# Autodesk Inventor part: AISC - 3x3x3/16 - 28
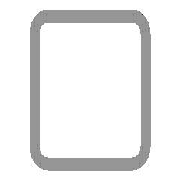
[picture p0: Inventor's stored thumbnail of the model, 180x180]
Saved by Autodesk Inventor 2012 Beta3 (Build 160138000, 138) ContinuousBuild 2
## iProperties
_CCFamilyMember: 9
_CCFamilyDisplayName: ANSI AISC (Square) - Tube
_FrameMemberDoc: Frame Member File
_Version: 15.0.0
_GetPNFromCC: 1
Created: 2010-11
Part Number: AISC - 3x3x3/16 - 28
Material: Steel, Mild
Description: Tube
Document SubType Name: Modeling
Standard: ANSI
Designer: Beta-8540w
Standards Organization: ANSI
Language: en-US
Size Designation: 3x3x3/16
Categories: <MemberInstance><Categories><Category DisplayName="Structural Shapes" InternalName="089c4875-fa83-4c05-b084-43b9cc11f5ed" Mnemonic="GRDR"><CategoryParameter Dis
Stock Number: 3x3x3/16
Density: 7.86 g/cm^3
IsCustomPart: 1
G_L: 28.000 in
G_W: 3.000 in
G_H: 3.000 in
Author: Beta-8540w
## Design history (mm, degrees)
node "Start plane"
node "End plane"
sketch "Sketch"
  geometry: L1 (-38.1, -28.575)-(-38.1, 28.575); L2 (-28.575, 38.1)-(28.575, 38.1); L3 (38.1, 28.575)-(38.1, -28.575); L4 (28.575, -38.1)-(-28.575, -38.1); L5 (-28.575, 33.337)-(28.575, 33.338); L6 (33.338, 28.575)-(33.338, -28.575); L7 (28.575, -33.337)-(-28.575, -33.338); L8 (-33.338, -28.575)-(-33.338, 28.575); L9 (0, 56.102)-(0, -56.102) reference; L10 (-56.102, 0)-(56.102, 0) reference; A1 r 9.525 centre (-28.575, -28.575) between (-38.1, -28.575) and (-28.575, -38.1); A2 r 9.525 centre (-28.575, 28.575) between (-28.575, 38.1) and (-38.1, 28.575); A3 r 9.525 centre (28.575, 28.575) between (38.1, 28.575) and (28.575, 38.1); A4 r 9.525 centre (28.575, -28.575) between (28.575, -38.1) and (38.1, -28.575); A5 r 4.763 centre (-28.575, 28.575) between (-28.575, 33.337) and (-33.338, 28.575); A6 r 4.763 centre (28.575, 28.575) between (33.338, 28.575) and (28.575, 33.338); A7 r 4.763 centre (28.575, -28.575) between (28.575, -33.337) and (33.338, -28.575); A8 r 4.763 centre (-28.575, -28.575) between (-33.338, -28.575) and (-28.575, -33.338)
  constraints: 16 end point, 16 point on circle, 8 centre point, 8 tangent, 4 parallel, 3 equal radius, 2 perpendicular, 7 other
  dimensions: "d10" = 76.2 distance between parallel lines of L2 L4 (= G_H); "d11" = 76.2 distance between parallel lines of L1 L3 (= G_W); "d12" = 4.7625 distance between parallel lines of L3 L6 (= G_T); "d15" = 38.1 distance between parallel lines of L2 L10 (= 0.5 x d10); "d16" = 38.1 distance between parallel lines of L9 L3 (= 0.5 x d11); "d17" = 9.525 radius of A1 (= G_IR)
extrude "Body" new body sketch "Sketch" stored distance "d3" = 711.2 (= G_L); taper "d4" = 0 deg
node "Driven Length"
  sketch "Sketch3"
    geometry: L1 (0, 0)-(10, 0) reference
    constraints: 2 end point, 1 horizontal
  workplane "Work Plane3"
  sketch "Sketch4"
    geometry: L1 (-2, 0)-(12, 0) reference; L2 (-2, 711.2)-(12, 711.2) reference
    dimensions: "d19" = 711.2 distance between parallel lines of L1 L2 (derived)
body "Solid1"
other parameters: "G_W" = 76.2 [user parameter; used in 1 equation term], "G_H" = 76.2 [user parameter; used in 1 equation term], "G_T" = 4.7625 [user parameter; used in 1 equation term], "G_IR" = 9.525 [user parameter; used in 1 equation term], "G_L" = 711.2 (= d19) [user parameter; used in 1 equation term], "G_OFFSET_START" = 0 [user parameter; used in 1 equation term], "G_OFFSET_END" = 0 [user parameter; used in 1 equation term], "d13" = 0 (computed from G_OFFSET_START), "d14" = 711.2 (= G_OFFSET_END + B_L), "B_L" = 711.2 [user parameter; used in 1 equation term], "d18" = 90 deg
